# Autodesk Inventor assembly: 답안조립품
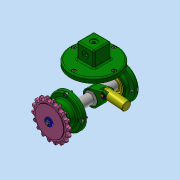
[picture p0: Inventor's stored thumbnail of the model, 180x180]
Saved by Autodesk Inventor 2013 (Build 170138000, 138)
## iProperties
Created: 2021-03
Part Number: 답안조립품
Document SubType Name: Assembly
Designer: Administrator
Author: Administrator
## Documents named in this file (19)
- C:\Users\Administrator\Desktop\710306V1002\답안조립품.iam
- C:\Users\Administrator\Desktop\710306V1002\본체.ipt
- C:\Users\Administrator\Desktop\710306V1002\볼트 M4 x 10.ipt
- C:\Users\Administrator\Desktop\710306V1002\베어링 17 x 40 x 12.ipt
- C:\Users\Administrator\Desktop\710306V1002\앞커버.ipt
- C:\Users\Administrator\Desktop\710306V1002\오일 실 17 30 8.ipt
- C:\Users\Administrator\Desktop\710306V1002\뒤커버.ipt
- C:\Users\Administrator\Desktop\710306V1002\덮개.ipt
- C:\Users\Administrator\Desktop\710306V1002\볼트 M4 x 8.ipt
- C:\Users\Administrator\Desktop\710306V1002\E-링.ipt
- C:\Users\Administrator\Desktop\710306V1002\스프로킷.ipt
- C:\Users\Administrator\Desktop\710306V1002\와셔 4x16.ipt
- C:\Users\Administrator\Desktop\710306V1002\키 4 x 4 x 12.ipt
- C:\Users\Administrator\Desktop\710306V1002\편심축.ipt
- C:\Users\Administrator\Desktop\710306V1002\멈춤나사 M3.ipt
- C:\Users\Administrator\Desktop\710306V1002\슬라이더.ipt
- C:\Users\Administrator\Desktop\710306V1002\클레비스 핀 6 x 22.ipt
- 클레비스 핀 6 x 22.ipt
- C:\Users\Administrator\Desktop\710306V1002\링크.ipt
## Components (1 placed, 1 different names)
1. E-링:1
